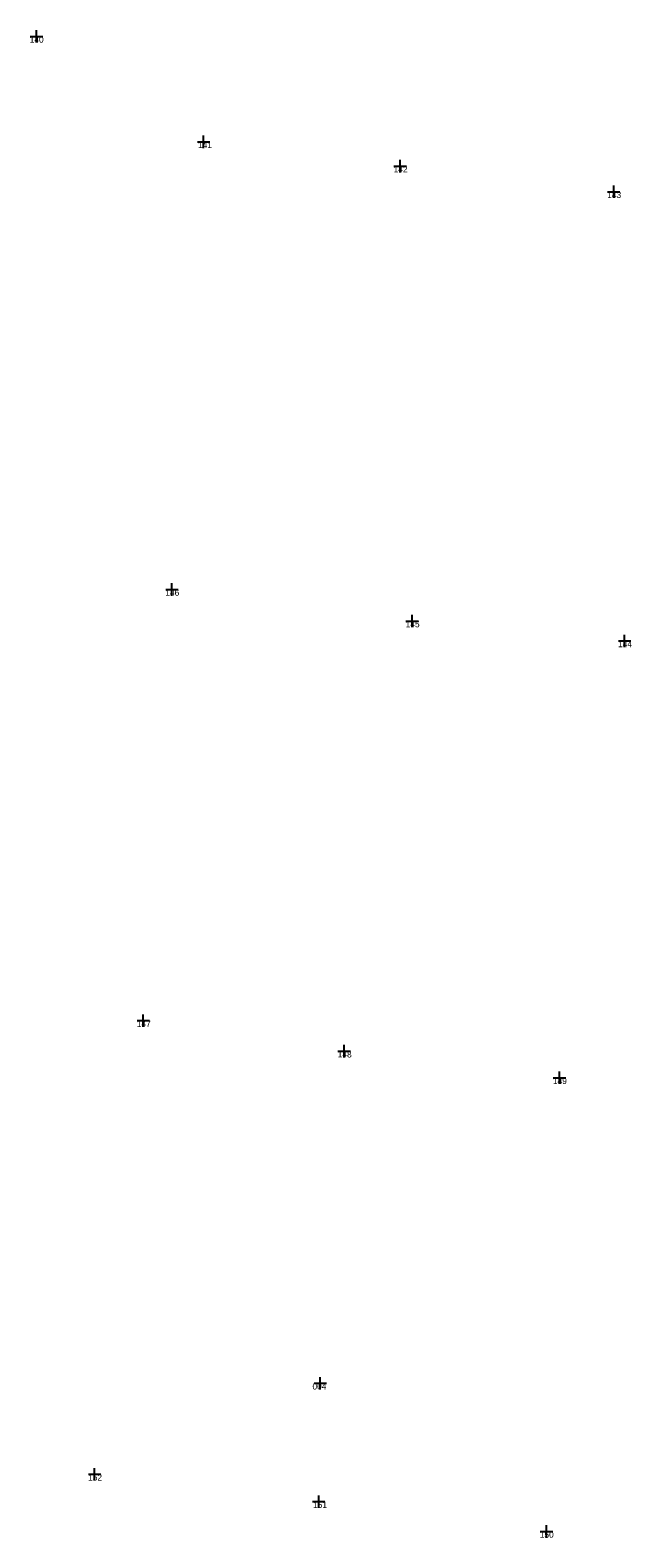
# Model space of a CAD drawing. Extents: x -706655 to -706193, y -1036183 to -1035040.
# Drawn here: x -706267.8 to -706219.7, y -1035891.3 to -1035770.7 of the extents above; entities that cross this region are included whole.
import ezdxf

# ---------------------------------------------------------------- set-up
doc = ezdxf.new("R2010")
doc.units = 0
doc.layers.add('čísla bodu', color=7, linetype='Continuous')

msp = doc.modelspace()

# ---------------------------------------------------------------- linework, layer by layer
at = {"layer": 'čísla bodu'}
for p, q in [((-706267.32, -1035771.65), (-706267.32, -1035770.65)), ((-706267.82, -1035771.15), (-706266.82, -1035771.15)), ((-706267.32, -1035771.15), (-706267.32, -1035771.15)), ((-706253.96, -1035780.09), (-706253.96, -1035779.09)), ((-706254.46, -1035779.59), (-706253.46, -1035779.59)), ((-706253.96, -1035779.59), (-706253.96, -1035779.59)), ((-706238.75, -1035781.53), (-706237.75, -1035781.53)), ((-706238.25, -1035782.03), (-706238.25, -1035781.03)), ((-706238.25, -1035781.53), (-706238.25, -1035781.53)), ((-706221.68, -1035783.58), (-706220.68, -1035783.58)), ((-706221.18, -1035784.08), (-706221.18, -1035783.08)), ((-706221.18, -1035783.58), (-706221.18, -1035783.58)), ((-706256.99, -1035815.41), (-706255.99, -1035815.41)), ((-706256.49, -1035815.91), (-706256.49, -1035814.91)), ((-706256.49, -1035815.41), (-706256.49, -1035815.41)), ((-706237.29, -1035818.43), (-706237.29, -1035817.43)), ((-706237.79, -1035817.93), (-706236.79, -1035817.93)), ((-706237.29, -1035817.93), (-706237.29, -1035817.93)), ((-706220.31, -1035820.02), (-706220.31, -1035819.02)), ((-706220.81, -1035819.52), (-706219.81, -1035819.52)), ((-706220.31, -1035819.52), (-706220.31, -1035819.52)), ((-706259.28, -1035849.9), (-706258.28, -1035849.9)), ((-706258.78, -1035850.4), (-706258.78, -1035849.4)), ((-706258.78, -1035849.9), (-706258.78, -1035849.9)), ((-706243.22, -1035852.35), (-706242.22, -1035852.35)), ((-706242.72, -1035852.85), (-706242.72, -1035851.85)), ((-706242.72, -1035852.35), (-706242.72, -1035852.35)), ((-706225.52, -1035854.97), (-706225.52, -1035853.97)), ((-706226.02, -1035854.47), (-706225.02, -1035854.47)), ((-706225.52, -1035854.47), (-706225.52, -1035854.47)), ((-706245.13, -1035878.92), (-706244.13, -1035878.92)), ((-706244.63, -1035879.42), (-706244.63, -1035878.42)), ((-706244.63, -1035878.92), (-706244.63, -1035878.92)), ((-706263.17, -1035886.2), (-706262.17, -1035886.2)), ((-706262.67, -1035886.7), (-706262.67, -1035885.7)), ((-706262.67, -1035886.2), (-706262.67, -1035886.2)), ((-706245.26, -1035888.39), (-706244.26, -1035888.39)), ((-706244.76, -1035888.89), (-706244.76, -1035887.89)), ((-706244.76, -1035888.39), (-706244.76, -1035888.39)), ((-706227.05, -1035890.78), (-706226.05, -1035890.78)), ((-706226.55, -1035891.28), (-706226.55, -1035890.28)), ((-706226.55, -1035890.78), (-706226.55, -1035890.78))]:
    msp.add_line(p, q, dxfattribs=at)

# ---------------------------------------------------------------- texts
for s, p in [('140', (-706267.86, -1035771.65)), ('141', (-706254.41, -1035780.09)), ('142', (-706238.77, -1035782.03)), ('143', (-706221.7, -1035784.08)), ('146', (-706257.02, -1035815.91)), ('145', (-706237.81, -1035818.43)), ('144', (-706220.83, -1035820.02)), ('147', (-706259.3, -1035850.4)), ('148', (-706243.24, -1035852.85)), ('149', (-706226.04, -1035854.97)), ('004', (-706245.26, -1035879.42)), ('152', (-706263.19, -1035886.7)), ('151', (-706245.21, -1035888.89)), ('150', (-706227.09, -1035891.28))]:
    msp.add_text(s, height=0.5, dxfattribs=at).set_placement(p)

doc.saveas('drawing.dxf')
